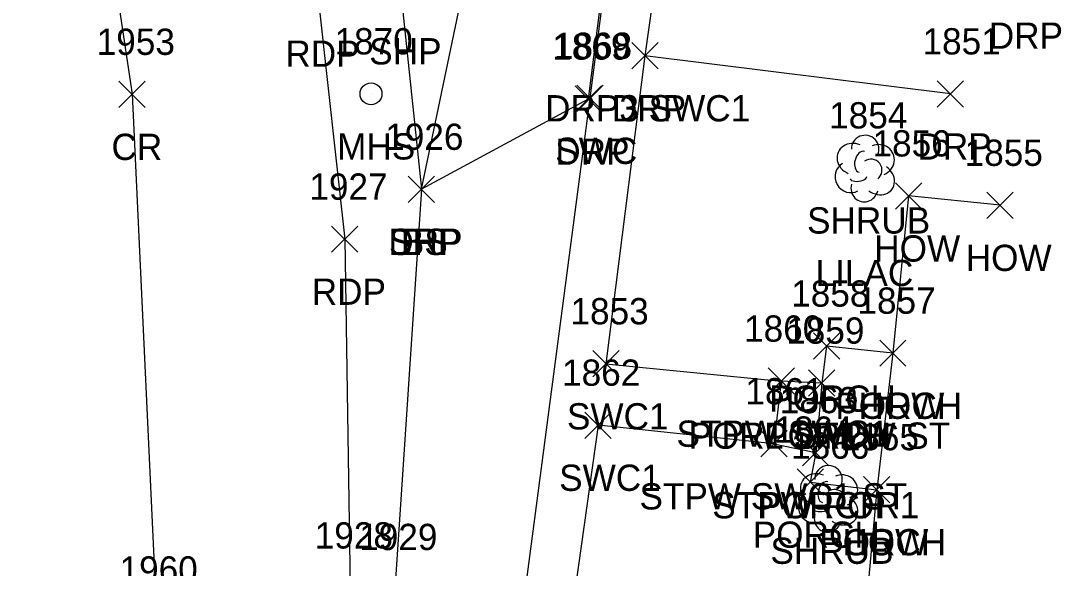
# Model space of a CAD drawing. Extents: x 1651305 to 1654558, y 539481 to 548441.
# Drawn here: x 1654376.5 to 1654455.6, y 544437.8 to 544479.5 of the extents above; entities that cross this region are included whole.
import ezdxf

# ---------------------------------------------------------------- set-up
doc = ezdxf.new("R2010")
doc.units = 0
for name, color, linetype in [('L_A', 7, 'Continuous'), ('L_C', 7, 'Continuous'), ('L_I', 7, 'Continuous'), ('L_TIC', 7, 'Continuous'), ('LBC', 7, 'Continuous'), ('LBF', 7, 'Continuous'), ('LELB', 7, 'Continuous'), ('LSH', 7, 'Continuous'), ('P_A', 7, 'Continuous'), ('P_I', 7, 'Continuous'), ('P_TIC', 7, 'Continuous'), ('PET', 7, 'Continuous'), ('PRC', 7, 'Continuous'), ('PSP', 7, 'Continuous'), ('R_A', 7, 'Continuous'), ('R_I', 7, 'Continuous'), ('R_TIC', 7, 'Continuous'), ('RDP', 7, 'Continuous'), ('RSW', 7, 'Continuous'), ('U_A', 7, 'Continuous'), ('U_I', 7, 'Continuous'), ('USMH', 7, 'Continuous')]:
    doc.layers.add(name, color=color, linetype=linetype)

msp = doc.modelspace()

# ---------------------------------------------------------------- linework, layer by layer
at = {"layer": 'L_TIC'}
for points in [[(1654405.951, 544465.687), (1654407.951, 544467.687)], [(1654407.951, 544465.687), (1654405.951, 544467.687)], [(1654443.011, 544465.184), (1654445.011, 544467.184)], [(1654445.011, 544465.184), (1654443.011, 544467.184)], [(1654449.965, 544464.468), (1654451.965, 544466.468)], [(1654451.965, 544464.468), (1654449.965, 544466.468)], [(1654436.773, 544453.754), (1654438.773, 544455.754)], [(1654438.773, 544453.754), (1654436.773, 544455.754)], [(1654441.811, 544453.213), (1654443.811, 544455.213)], [(1654443.811, 544453.213), (1654441.811, 544455.213)], [(1654441.811, 544453.213), (1654443.811, 544455.213)], [(1654443.811, 544453.213), (1654441.811, 544455.213)], [(1654433.323, 544451.087), (1654435.323, 544453.087)], [(1654435.323, 544451.087), (1654433.323, 544453.087)], [(1654436.4, 544450.937), (1654438.4, 544452.937)], [(1654438.4, 544450.937), (1654436.4, 544452.937)], [(1654436.4, 544450.937), (1654438.4, 544452.937)], [(1654438.4, 544450.937), (1654436.4, 544452.937)], [(1654432.769, 544446.317), (1654434.769, 544448.317)], [(1654434.769, 544446.317), (1654432.769, 544448.317)], [(1654435.951, 544445.642), (1654437.951, 544447.642)], [(1654437.951, 544445.642), (1654435.951, 544447.642)], [(1654435.951, 544445.642), (1654437.951, 544447.642)], [(1654437.951, 544445.642), (1654435.951, 544447.642)], [(1654435.532, 544443.4), (1654437.532, 544445.4)], [(1654437.532, 544443.4), (1654435.532, 544445.4)], [(1654440.59, 544442.825), (1654442.59, 544444.825)], [(1654442.59, 544442.825), (1654440.59, 544444.825)], [(1654440.59, 544442.825), (1654442.59, 544444.825)], [(1654442.59, 544442.825), (1654440.59, 544444.825)]]:
    msp.add_lwpolyline(points, dxfattribs=at)
at = {"layer": 'LBC'}
msp.add_lwpolyline([(1654450.965, 544465.468), (1654444.011, 544466.184), (1654442.811, 544454.213), (1654441.59, 544443.825), (1654440.479, 544431.714), (1654442.535, 544431.51), (1654444.157, 544426.366), (1654450.144, 544425.661)], dxfattribs=at)
at = {"layer": 'LBF'}
for points in [[(1654442.811, 544454.213), (1654437.773, 544454.754), (1654437.4, 544451.937), (1654436.951, 544446.642), (1654436.532, 544444.4), (1654441.59, 544443.825)], [(1654437.4, 544451.937), (1654434.323, 544452.087), (1654433.769, 544447.317), (1654436.951, 544446.642)]]:
    msp.add_lwpolyline(points, dxfattribs=at)
at = {"layer": 'LELB'}
msp.add_lwpolyline([(1654406.951, 544466.687), (1654414.004, 544500.453), (1654417.578, 544536.277), (1654418.757, 544565.929), (1654410.195, 544609.107), (1654409.857, 544614.549), (1654405.7, 544641.925)], dxfattribs=at)
at = {"layer": 'LSH'}
for p, q in [((1654440.658, 544468.317), (1654440.658, 544468.317)), ((1654440.658, 544468.317), (1654440.658, 544468.317)), ((1654437.868, 544443.179), (1654437.868, 544443.179)), ((1654437.868, 544443.179), (1654437.868, 544443.179))]:
    msp.add_line(p, q, dxfattribs=at)
for centre in [(1654440.704, 544469.751), (1654437.915, 544444.613)]:
    msp.add_arc(centre, 1.047, 335.52715, 180.95627, dxfattribs=at)
for centre, major_axis, ratio, start_param, end_param in [((1654439.866, 544468.984), (1.21, -0.512), 0.895232, 1.570796, 4.712389), ((1654441.699, 544468.901), (-1.141, -0.483), 0.949671, 1.570796, 4.712389), ((1654440.449, 544468.776), (-0.208, -0.792), 0.645439, 3.141593, 6.283185), ((1654439.574, 544467.609), (0.584, -1.042), 0.959034, 3.141593, 6.283185), ((1654441.158, 544468.151), (-0.5, 0.667), 0.989748, 3.141593, 6.283185), ((1654441.658, 544467.484), (-1.09, 0.792), 0.841452, 1.570796, 4.712389), ((1654440.658, 544466.817), (0.265, 1.061), 0.942809, 1.570796, 4.712389), ((1654440.199, 544467.567), (-0.625, -0.083), 0.423636, 0, 3.141593), ((1654437.077, 544443.846), (1.21, -0.512), 0.895232, 1.570796, 4.712389), ((1654438.91, 544443.762), (-1.141, -0.483), 0.949671, 1.570796, 4.712389), ((1654437.66, 544443.637), (-0.208, -0.792), 0.645439, 3.141593, 6.283185), ((1654436.785, 544442.47), (0.584, -1.042), 0.959034, 3.141593, 6.283185), ((1654438.369, 544443.012), (-0.5, 0.667), 0.989748, 3.141593, 6.283185), ((1654438.869, 544442.346), (-1.09, 0.792), 0.841452, 1.570796, 4.712389), ((1654437.41, 544442.429), (-0.625, -0.083), 0.423636, 0, 3.141593), ((1654437.869, 544441.679), (0.265, 1.061), 0.942809, 1.570796, 4.712389)]:
    msp.add_ellipse(centre, major_axis=major_axis, ratio=ratio, start_param=start_param, end_param=end_param, dxfattribs=at)
at = {"layer": 'P_TIC'}
for points in [[(1654383.95, 544472.916), (1654385.95, 544474.916)], [(1654385.95, 544472.916), (1654383.95, 544474.916)], [(1654405.951, 544465.687), (1654407.951, 544467.687)], [(1654407.951, 544465.687), (1654405.951, 544467.687)], [(1654400.125, 544461.893), (1654402.125, 544463.893)], [(1654402.125, 544461.893), (1654400.125, 544463.893)]]:
    msp.add_lwpolyline(points, dxfattribs=at)
at = {"layer": 'PET'}
msp.add_lwpolyline([(1654345.042, 544588.36), (1654350.59, 544607.191), (1654356.582, 544624.309), (1654366.692, 544597.705), (1654378.699, 544565.627), (1654388.798, 544536.019), (1654394.392, 544506.433), (1654399.121, 544481.008), (1654401.125, 544462.893), (1654401.531, 544436.346), (1654401.825, 544421.309), (1654397.366, 544359.696), (1654394.392, 544336.586), (1654391.404, 544308.963), (1654388.941, 544290.736), (1654386.845, 544274.06), (1654380.974, 544229.445), (1654377.749, 544202.908), (1654375.628, 544181.037), (1654372.192, 544149.754), (1654366.612, 544105.723), (1654362.798, 544072.788)], dxfattribs=at)
at = {"layer": 'PRC'}
msp.add_lwpolyline([(1654350.59, 544607.191), (1654355.931, 544592.699), (1654363.685, 544570.628), (1654372.223, 544542.272), (1654380.244, 544505.389), (1654384.95, 544473.916), (1654386.821, 544433.75), (1654385.713, 544395.522), (1654383.86, 544365.997), (1654380.919, 544339.646), (1654377.996, 544311.086), (1654373.889, 544274.842), (1654369.008, 544231.012), (1654366.63, 544212.463), (1654362.444, 544177.974), (1654359.488, 544151.886), (1654354.071, 544107.932), (1654348.42, 544063.008)], dxfattribs=at)
at = {"layer": 'PSP'}
msp.add_lwpolyline([(1654388.798, 544536.019), (1654393.152, 544530.334), (1654397.052, 544530.18), (1654401.661, 544509.48), (1654405.45, 544481.191), (1654406.951, 544466.687), (1654404.923, 544436.226), (1654404.117, 544420.923), (1654397.366, 544359.696)], dxfattribs=at)
at = {"layer": 'R_TIC'}
for points in [[(1654422.952, 544475.853), (1654424.952, 544477.853)], [(1654424.952, 544475.853), (1654422.952, 544477.853)], [(1654422.952, 544475.853), (1654424.952, 544477.853)], [(1654424.952, 544475.853), (1654422.952, 544477.853)], [(1654446.193, 544472.948), (1654448.193, 544474.948)], [(1654448.193, 544472.948), (1654446.193, 544474.948)], [(1654418.649, 544472.553), (1654420.649, 544474.553)], [(1654420.649, 544472.553), (1654418.649, 544474.553)], [(1654418.77, 544472.615), (1654420.77, 544474.615)], [(1654420.77, 544472.615), (1654418.77, 544474.615)], [(1654405.951, 544465.687), (1654407.951, 544467.687)], [(1654407.951, 544465.687), (1654405.951, 544467.687)], [(1654419.985, 544452.407), (1654421.985, 544454.407)], [(1654421.985, 544452.407), (1654419.985, 544454.407)], [(1654433.323, 544451.087), (1654435.323, 544453.087)], [(1654435.323, 544451.087), (1654433.323, 544453.087)], [(1654419.392, 544447.732), (1654421.392, 544449.732)], [(1654421.392, 544447.732), (1654419.392, 544449.732)], [(1654432.769, 544446.317), (1654434.769, 544448.317)], [(1654434.769, 544446.317), (1654432.769, 544448.317)]]:
    msp.add_lwpolyline(points, dxfattribs=at)
at = {"layer": 'RDP'}
for points in [[(1654432.453, 544721.26), (1654412.473, 544723.068), (1654409.324, 544720.532), (1654406.192, 544714.273), (1654402.612, 544671.581), (1654403.27, 544666.414), (1654406.853, 544662.099), (1654407.381, 544661.789), (1654407.089, 544658.718), (1654407.855, 544657.75), (1654443.015, 544654.447), (1654438.677, 544619.923), (1654433.469, 544580.157), (1654430.086, 544554.066), (1654427.975, 544537.224), (1654424.616, 544512.8), (1654419.649, 544473.553), (1654406.951, 544466.687)], [(1654447.193, 544473.948), (1654423.952, 544476.853)]]:
    msp.add_lwpolyline(points, dxfattribs=at)
at = {"layer": 'RSW'}
for points in [[(1654407.404, 544661.775), (1654407.293, 544658.868), (1654407.962, 544657.877), (1654443.269, 544654.592), (1654438.81, 544619.894), (1654433.558, 544580.17), (1654430.136, 544553.995), (1654428.025, 544537.281), (1654424.833, 544512.838), (1654419.77, 544473.615), (1654412.659, 544419.662), (1654404.122, 544354.774), (1654402.102, 544339.773), (1654395.487, 544286.058), (1654394.013, 544276.122), (1654388.386, 544229.583), (1654383.891, 544196.376), (1654382.201, 544184.333), (1654378.352, 544149.148), (1654372.361, 544105.495), (1654368.546, 544072.052)], [(1654440.199, 544511.478), (1654431.777, 544512.392), (1654428.832, 544512.647), (1654425.384, 544487.13), (1654423.952, 544476.853), (1654420.985, 544453.407), (1654434.323, 544452.087)], [(1654433.769, 544447.317), (1654420.392, 544448.732), (1654416.298, 544419.47), (1654415.224, 544408.685), (1654412.657, 544388.617), (1654423.018, 544387.519), (1654429.579, 544386.827), (1654429.097, 544382.97), (1654422.687, 544383.714), (1654411.983, 544384.286), (1654408, 544354.107), (1654405.993, 544338.287), (1654403.211, 544318.213), (1654402.851, 544314.962), (1654399.432, 544285.106), (1654398.089, 544275.966), (1654392.335, 544231.256), (1654397.808, 544230.762), (1654412.219, 544229.296)]]:
    msp.add_lwpolyline(points, dxfattribs=at)
at = {"layer": 'USMH'}
for p, q in [((1654403.123, 544473.954), (1654403.123, 544473.954)), ((1654403.956, 544473.954), (1654403.956, 544473.954))]:
    msp.add_line(p, q, dxfattribs=at)
msp.add_circle((1654403.123, 544473.954), 0.833, dxfattribs=at)

# ---------------------------------------------------------------- texts
at = {"layer": 'L_A'}
for s, p in [('SHRUB', (1654436.288, 544463.317)), ('BS', (1654405.392, 544461.687)), ('HOW', (1654441.397, 544461.184)), ('HOW', (1654448.351, 544460.468)), ('PORCH', (1654433.395, 544449.754)), ('PORCH', (1654438.433, 544449.213)), ('HOW', (1654440.197, 544449.213)), ('STPW SWC1', (1654426.354, 544447.087)), ('POR1 STPW ST', (1654427.266, 544446.937)), ('PORCH', (1654433.022, 544446.937)), ('STPW SWC1 ST', (1654423.541, 544442.317)), ('STPW POR1', (1654429.077, 544441.642)), ('PORCH', (1654432.573, 544441.642)), ('PORCH', (1654432.154, 544439.4)), ('SHRUB', (1654433.498, 544438.179)), ('PORCH', (1654437.212, 544438.825)), ('HOW', (1654438.976, 544438.825))]:
    msp.add_text(s, height=2, dxfattribs=at).set_placement(p)
at = {"layer": 'L_C'}
msp.add_text('LILAC', height=2, dxfattribs=at).set_placement((1654436.933, 544459.317))
at = {"layer": 'L_I'}
for s, p in [('1854', (1654437.965, 544471.317)), ('1926', (1654404.203, 544469.687)), ('1856', (1654441.263, 544469.184)), ('1855', (1654448.272, 544468.468)), ('1858', (1654435.08, 544457.754)), ('1857', (1654440.118, 544457.213)), ('1857', (1654440.118, 544457.213)), ('1860', (1654431.496, 544455.087)), ('1859', (1654434.699, 544454.937)), ('1859', (1654434.699, 544454.937)), ('1861', (1654431.596, 544450.317)), ('1863', (1654434.211, 544449.642)), ('1863', (1654434.211, 544449.642)), ('1864', (1654433.792, 544447.4)), ('1865', (1654438.85, 544446.825)), ('1865', (1654438.85, 544446.825)), ('1866', (1654435.073, 544446.179))]:
    msp.add_text(s, height=2, dxfattribs=at).set_placement(p)
at = {"layer": 'P_A'}
for s, p in [('SHP', (1654402.986, 544476.191)), ('RDP', (1654396.609, 544476.008)), ('CR', (1654383.383, 544468.916)), ('SHP', (1654404.486, 544461.687)), ('RDP', (1654398.614, 544457.893))]:
    msp.add_text(s, height=2, dxfattribs=at).set_placement(p)
at = {"layer": 'P_I'}
for s, p in [('1953', (1654382.257, 544476.916)), ('1926', (1654404.203, 544469.687)), ('1927', (1654398.433, 544465.893)), ('1928', (1654398.839, 544439.346)), ('1929', (1654402.222, 544439.226)), ('1960', (1654383.994, 544436.75))]:
    msp.add_text(s, height=2, dxfattribs=at).set_placement(p)
at = {"layer": 'R_A'}
for s, p in [('DRP', (1654450.109, 544477.378)), ('DRP3 SWC1', (1654416.361, 544471.853)), ('DRP', (1654421.44, 544471.853)), ('DRP', (1654444.681, 544468.948)), ('SWC', (1654417.132, 544468.615)), ('DRP', (1654417.138, 544468.553)), ('DRP', (1654404.439, 544461.687)), ('SWC1', (1654418.024, 544448.407)), ('STPW SWC1', (1654426.354, 544447.087)), ('SWC1', (1654417.432, 544443.732)), ('STPW SWC1 ST', (1654423.541, 544442.317))]:
    msp.add_text(s, height=2, dxfattribs=at).set_placement(p)
at = {"layer": 'R_I'}
for s, p in [('1851', (1654445.067, 544476.948)), ('1869', (1654416.902, 544476.553)), ('1868', (1654417.03, 544476.615)), ('1926', (1654404.203, 544469.687)), ('1853', (1654418.292, 544456.407)), ('1860', (1654431.496, 544455.087)), ('1862', (1654417.652, 544451.732)), ('1861', (1654431.596, 544450.317))]:
    msp.add_text(s, height=2, dxfattribs=at).set_placement(p)
at = {"layer": 'U_A'}
msp.add_text('MHS', height=2, dxfattribs=at).set_placement((1654400.54, 544468.954))
at = {"layer": 'U_I'}
msp.add_text('1870', height=2, dxfattribs=at).set_placement((1654400.344, 544476.954))

doc.saveas('drawing.dxf')
